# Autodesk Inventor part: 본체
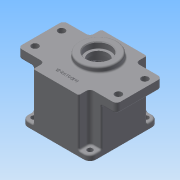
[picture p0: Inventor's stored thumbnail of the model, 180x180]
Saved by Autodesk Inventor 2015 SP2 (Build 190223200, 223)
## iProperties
Created: 2015-06
Part Number: 본체
Material: 일반
Document SubType Name: Modeling
Designer: AMC
Density: 1 g/cm^3
Appearance: 기본값
Author: AMC
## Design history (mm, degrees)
sketch "스케치1"
  geometry: L1 (-45, 45)-(45, 45); L2 (45, 45)-(45, -45); L3 (45, -45)-(-45, -45); L4 (-45, -45)-(-45, 45); 3 further points
  constraints: 8 end point, 2 midpoint, 2 parallel, 1 horizontal, 1 horizontal alignment, 1 perpendicular, 1 vertical alignment
  dimensions: "d6" = 90 distance of L2.end L3.end; "d7" = 90 distance of L3.end L1.start
extrude "돌출1" new body sketch "스케치1" distance "d8" = 7; taper "d9" = 0 deg
sketch "스케치11"
  geometry: L1 (-45, 45)-(-45, -45) reference; L2 (-45, 30)-(-45, -30); L3 (-45, -30)-(-30, -30); L4 (-30, -30)-(-30, -45); L5 (-45, -45)-(45, -45) reference; L6 (-30, -45)-(30, -45); L7 (30, -45)-(30, -30); L8 (30, -30)-(45, -30); L9 (45, -45)-(45, 45) reference; L10 (45, -30)-(45, 30); L11 (45, 30)-(30, 30); L12 (30, 30)-(30, 45); L13 (45, 45)-(-45, 45) reference; L14 (30, 45)-(-30, 45); L15 (-30, 45)-(-30, 30); L16 (-30, 30)-(-45, 30); 5 further points
  constraints: 24 end point, 13 point on line, 4 midpoint, 4 perpendicular, 3 horizontal alignment, 1 horizontal, 1 vertical alignment
  dimensions: "d47" = 60 distance between parallel lines of L3 L16; "d48" = 60 distance between parallel lines of L8 L11; "d49" = 60 distance between parallel lines of L12 L15
extrude "돌출9" join sketch "스케치11" distance "d50" = 51; taper "d51" = 0 deg
sketch "스케치12"
  geometry: L1 (-30, -45)-(-30, -30) reference; L2 (-30, -30)-(-45, -30) reference; L3 (-45, -30)-(-45, 30) reference; L4 (-45, 30)-(-30, 30) reference; L5 (-30, 30)-(-30, 45) reference; L6 (-30, 45)-(30, 45) reference; L7 (30, 45)-(30, 30) reference; L8 (30, 30)-(45, 30) reference; L9 (45, 30)-(45, -30) reference; L10 (45, -30)-(30, -30) reference; L11 (30, -30)-(30, -45) reference; L12 (30, -45)-(-30, -45) reference; L13 (-65, -30)-(65, -30); L14 (65, -30)-(65, 30); L15 (65, 30)-(-65, 30); L16 (-65, 30)-(-65, -30); L17 (-30, 45)-(30, 45); L18 (30, 45)-(30, -45); L19 (30, -45)-(-30, -45); L20 (-30, -45)-(-30, 45); 3 further points
  constraints: 16 end point, 4 parallel, 2 horizontal, 2 midpoint, 2 perpendicular, 1 horizontal alignment, 1 vertical alignment
  dimensions: "d52" = 130 distance of L13.start L13.end; "d53" = 60 distance of L15.end L13.start
  node "절단 모서리 투영5"
extrude "돌출10" join sketch "스케치12" distance "d54" = 12; taper "d55" = 0 deg
extrude "돌출11" join sketch "스케치12" distance "d56" = 12; taper "d57" = 0 deg
sketch "스케치13"
  geometry: C1 r 25 at (0, 11); 1 further point
  constraints: 1 centre point, 1 vertical alignment
  dimensions: "d58" = 50 diameter of C1; "d59" = 11 distance of point (0, 0) C1.centre
extrude "돌출12" join sketch "스케치13" distance "d60" = 7; taper "d61" = 0 deg
sketch "스케치14"
  geometry: L1 (36, 77)-(36, 70) reference; L2 (36, 70)-(45, 70) reference; L3 (45, 70)-(45, 0) reference; L4 (45, 0)-(-45, 0) reference; L5 (-45, 0)-(-45, 70) reference; L6 (-45, 70)-(-14, 70) reference; L7 (-14, 70)-(-14, 77) reference; L8 (-14, 77)-(36, 77) reference; L9 (36, 77)-(-14, 77) reference; L10 (11, 77)-(11, 54); L11 (11, 54)-(28.5, 54); L12 (28.5, 54)-(28.5, 64); L13 (28.5, 64)-(23.5, 64); L14 (23.5, 64)-(23.5, 69); L15 (23.5, 69)-(27, 69); L16 (27, 69)-(27, 77); L17 (27, 77)-(11, 77); 1 further point
  constraints: 16 end point, 6 perpendicular, 1 collinear, 1 midpoint, 1 point on line, 1 vertical
  dimensions: "d62" = 32 diameter of L16 L10; "d63" = 25 diameter of L14 L10; "d64" = 35 diameter of L12 L10; "d65" = 23 distance between parallel lines of L8 L11; "d66" = 8 distance between parallel lines of L17 L15; "d67" = 5 distance between parallel lines of L15 L13
revolve "회전2" sketch "스케치14" stored, may be unused: angle "d68" = 90 deg
sketch "스케치15"
  geometry: C1 r 40 at (0, 0); C2 r 39 at (0, 0); 1 further point
  constraints: 2 centre point, 2 coincident
  dimensions: "d69" = 80 diameter of C1; "d70" = 78 diameter of C2
extrude "돌출13" cut sketch "스케치15" distance "d71" = 61; taper "d72" = 0 deg
extrude "돌출14" cut sketch "스케치15" distance "d73" = 9; taper "d74" = 0 deg
sketch "스케치16"
  geometry: L1 (-65, 30)-(-30, 30) reference; L2 (-30, 30)-(-30, 45) reference; L3 (-30, 45)-(30, 45) reference; L4 (30, 45)-(30, 30) reference; L5 (30, 30)-(65, 30) reference; L6 (65, 30)-(65, -30) reference; L7 (65, -30)-(30, -30) reference; L8 (30, -45)-(-30, -45) reference; L9 (-30, -30)-(-65, -30) reference; L10 (-65, -30)-(-65, 30) reference; L11 (30, -30)-(30, -45) reference; L12 (-30, -45)-(-30, -30) reference; C1 r 20.5 at (0, 11); C2 r 39 at (0, 0) reference; C3 r 17.5 at (0, 11) reference; A1 r 14 centre (0, -20) between (-2.777, -6.278) and (2.777, -6.278); A2 r 17.5 centre (0, 11) between (2.777, -6.278) and (-2.777, -6.278); 1 further point
  constraints: 4 point on circle, 3 centre point, 2 vertical alignment, 1 coincident
  dimensions: "d77" = 11 distance of point (0, 0) C1.centre; "d78" = 20 distance of A1.centre point (0, 0); "d91" = 14 radius of A1; "d92" = 20.5 radius of C1; "d93" = 35 diameter of A2
extrude "돌출15" join sketch "스케치16" distance "d79" = 7; taper "d80" = 0 deg
sketch "스케치17"
  geometry: L1 (30, 30)-(45, 30) reference; L2 (45, 30)-(45, -30) reference; L3 (45, -30)-(30, -30) reference; L4 (30, -45)-(-30, -45) reference; L5 (-30, -30)-(-45, -30) reference; L6 (-45, -30)-(-45, 30) reference; L7 (-45, 30)-(-30, 30) reference; L8 (-30, 30)-(-30, 45) reference; L9 (-30, 45)-(30, 45) reference; L10 (30, 45)-(30, 30) reference; L11 (30, -30)-(30, -45) reference; L12 (-30, -45)-(-30, -30) reference; C1 r 17.5 at (0, 11) reference; C2 r 39 at (0, 0) reference; C3 r 11 at (0, -20); A1 r 20.5 centre (0, 11) between (7.402, -8.117) and (-7.402, -8.117) reference; A2 r 14 centre (0, -20) between (-7.402, -8.117) and (7.402, -8.117) reference; 2 further points
  constraints: 1 centre point, 1 coincident
  dimensions: "d90" = 22 diameter of C3
  node "절단 모서리 투영8"
extrude "돌출16" cut sketch "스케치17" distance "d95" = 7; taper "d96" = 0 deg
sketch "스케치18"
  geometry: L1 (-65, 50)-(-30, 50) reference; L2 (-30, 50)-(-30, 65) reference; L3 (-30, 65)-(30, 65) reference; L4 (30, 65)-(30, 50) reference; L5 (30, 50)-(65, 50) reference; L6 (65, 50)-(65, -10) reference; L7 (65, -10)-(30, -10) reference; L8 (30, -25)-(-30, -25) reference; L9 (-30, -10)-(-65, -10) reference; L10 (-65, -10)-(-65, 50) reference; L11 (30, -10)-(30, -25) reference; L12 (-30, -25)-(-30, -10) reference; C1 r 11 at (0, 0) reference; C2 r 39 at (0, 20) reference; C3 r 17.5 at (0, 31) reference; C4 r 9.5 at (0, 0); A1 r 20.5 centre (0, 31) between (7.402, 11.883) and (-7.402, 11.883) reference; A2 r 14 centre (0, 0) between (-7.402, 11.883) and (7.402, 11.883) reference; 1 further point
  constraints: 1 centre point, 1 coincident
  dimensions: "d97" = 19 diameter of C4
extrude "돌출17" cut sketch "스케치18" distance "d98" = 1; taper "d99" = 0 deg
sketch "스케치20"
  geometry: L1 (-65, 30)-(-30, 30) reference; L2 (-30, 30)-(-30, 45) reference; L3 (-30, 45)-(30, 45) reference; L4 (30, 45)-(30, 30) reference; L5 (30, 30)-(65, 30) reference; L6 (65, 30)-(65, -30) reference; L7 (65, -30)-(30, -30) reference; L8 (30, -45)-(-30, -45) reference; L9 (-30, -30)-(-65, -30) reference; L10 (-65, -30)-(-65, 30) reference; L11 (24.749, -24.749)-(0, 0); L12 (0, 0)-(29.346, 0); L13 (27.411, -21.763)-(30.401, -24.429); L14 (21.763, -27.411)-(24.789, -30.109); L15 (30, -30)-(30, -45) reference; L16 (-30, -45)-(-30, -30) reference; C1 r 9.5 at (0, -20) reference; C2 r 11 at (0, -20) reference; C3 r 17.5 at (0, 11) reference; A1 r 20.5 centre (0, 11) between (7.402, -8.117) and (-7.402, -8.117) reference; A2 r 14 centre (0, -20) between (-7.402, -8.117) and (7.402, -8.117) reference; A3 r 39 centre (0, 0) between (30.401, -24.429) and (24.789, -30.109) reference; A4 r 35 centre (0, 0) between (24.749, -24.749) and (27.411, -21.763); A5 r 4 centre (24.749, -24.749) between (27.411, -21.763) and (21.763, -27.411); 1 further point
  constraints: 8 end point, 7 point on circle, 2 centre point, 1 coincident, 1 horizontal, 1 parallel, 1 tangent
  dimensions: "d113" = 70 diameter of A4; "d114" = 8 diameter of A5; "d115" = 45 deg angle of L12 L11
extrude "돌출18" join sketch "스케치20" distance "d116" = 52; taper "d117" = 0 deg
hole "구멍2" diameter "d123" = 3.459; stored, may be unused: countersink angle "d127" = 90 deg, drill point angle "d129" = 118 deg; dims "d121" = 10, "d122" = 10, "d124" = 12, "d125" = 22, "d126" = 7, "d128" = 15
fillet "모깎기1" dims "d133" = 2
fillet "모깎기2" dims "d134" = 0.3
chamfer "모따기1" distance "d135" = 1; stored, may be unused: second distance "d136" = 2, angle "d137" = 45 deg
fillet "모깎기3" dims "d140" = 3
fillet "모깎기4" dims "d141" = 2
fillet "모깎기7" dims "d144" = 5
fillet "모깎기8" dims "d145" = 8
sketch "스케치22"
  geometry: L1 (30, 30)-(60, 30) reference; L2 (65, 25)-(65, -25) reference; L3 (-65, -25)-(-65, 25) reference; L4 (60, -30)-(30, -30) reference; L5 (30, -30)-(30, -45) reference; L6 (30, -45)-(-30, -45) reference; L7 (-30, -30)-(-60, -30) reference; L8 (-60, 30)-(-30, 30) reference; L9 (-30, 30)-(-30, 45) reference; L10 (-30, 45)-(30, 45) reference; L11 (30, 45)-(30, 30) reference; L12 (-30, -45)-(-30, -30) reference; L13 (-55, 17.5)-(-55, -17.5); L14 (55, 17.5)-(55, -17.5); C1 r 16 at (0, 11) reference; C2 r 27 at (0, 11) reference; C3 r 4.5 at (-55, 17.5); C4 r 4.5 at (-55, -17.5); C5 r 4.5 at (55, 17.5); C6 r 4.5 at (55, -17.5); A1 r 5 centre (60, 25) between (65, 25) and (60, 30) reference; A2 r 5 centre (60, -25) between (60, -30) and (65, -25) reference; A3 r 5 centre (-60, -25) between (-65, -25) and (-60, -30) reference; A4 r 5 centre (-60, 25) between (-60, 30) and (-65, 25) reference; 3 further points
  constraints: 4 centre point, 4 end point, 2 horizontal alignment, 2 midpoint, 2 vertical, 2 vertical alignment
  dimensions: "d160" = 9 diameter of C3; "d161" = 9 diameter of C4; "d162" = 35 distance of L13.end L13.start; "d163" = 10 distance from line of L13.start L3; "d164" = 9 diameter of C5; "d165" = 9 diameter of C6; "d166" = 35 distance of L14.end L14.start; "d167" = 10 distance from line of L14.start L2
  node "절단 모서리 투영13"
fillet "모깎기11" dims "d155" = 3.5
fillet "모깎기12" dims "d156" = 2
fillet "모깎기13" dims "d157" = 5
fillet "모깎기14" dims "d158" = 2
extrude "돌출19" cut sketch "스케치22" stored distance "d168" = 52; taper "d169" = 0 deg
sketch "스케치23"
  geometry: L1 (37, 43)-(32, 43) reference; L2 (43, 32)-(43, 37) reference; L3 (45, 28.536)-(45, -28.536) reference; L4 (43, -37)-(43, -32) reference; L5 (32, -43)-(37, -43) reference; L6 (28.536, -45)-(-28.536, -45) reference; L7 (-37, -43)-(-32, -43) reference; L8 (-43, -32)-(-43, -37) reference; L9 (-45, -28.536)-(-45, 28.536) reference; L10 (-43, 37)-(-43, 32) reference; L11 (-32, 43)-(-37, 43) reference; L12 (-28.536, 45)-(28.536, 45) reference; L13 (32, 35)-(32, 43) reference; L14 (43, 32)-(35, 32) reference; L15 (35, -32)-(43, -32) reference; L16 (32, -43)-(32, -35) reference; L17 (-32, -35)-(-32, -43) reference; L18 (-43, -32)-(-35, -32) reference; L19 (-35, 32)-(-43, 32) reference; L20 (-32, 43)-(-32, 35) reference; C1 r 40 at (0, 0) reference; C2 r 3.5 at (-37, 37); C3 r 3.5 at (-37, -37); C4 r 3.5 at (37, -37); C5 r 3.5 at (37, 37); A1 r 6 centre (37, 37) between (43, 37) and (37, 43) reference; A2 r 6 centre (37, -37) between (37, -43) and (43, -37) reference; A3 r 6 centre (-37, -37) between (-43, -37) and (-37, -43) reference; A4 r 6 centre (-37, 37) between (-37, 43) and (-43, 37) reference; A5 r 3 centre (35, 35) between (32, 35) and (35, 32) reference; A6 r 3 centre (35, -35) between (35, -32) and (32, -35) reference; A7 r 3 centre (-35, -35) between (-32, -35) and (-35, -32) reference; A8 r 3 centre (-35, 35) between (-35, 32) and (-32, 35) reference; 1 further point
  constraints: 4 centre point, 4 coincident, 8 other
  dimensions: "d170" = 7 diameter of C2; "d171" = 7 diameter of C3; "d172" = 7 diameter of C4; "d173" = 7 diameter of C5
extrude "돌출20" cut sketch "스케치23" stored distance "d174" = 52; taper "d175" = 0 deg
sketch "스케치24"
  geometry: L1 (-28, -45)-(28, -45) reference; 2 further points
  constraints: 1 vertical alignment, 1 other
  dimensions: "d176" = 15 distance from line of L1 point (0, -30)
feature "엠보싱1" sketch "스케치24" dims "d47" = 60, "d48" = 60, "d49" = 60, "d177" = 0.5, "d178" = 0
node "솔리드1"
pattern_circular "원형 패턴1" dims angle "d119" = 360 deg
pattern_circular "원형 패턴2" dims angle "d131" = 360 deg
node "절단 모서리 투영6"
node "절단 모서리 투영7"
node "절단 모서리 투영9"
node "절단 모서리 투영11"
node "절단 모서리 투영14"
